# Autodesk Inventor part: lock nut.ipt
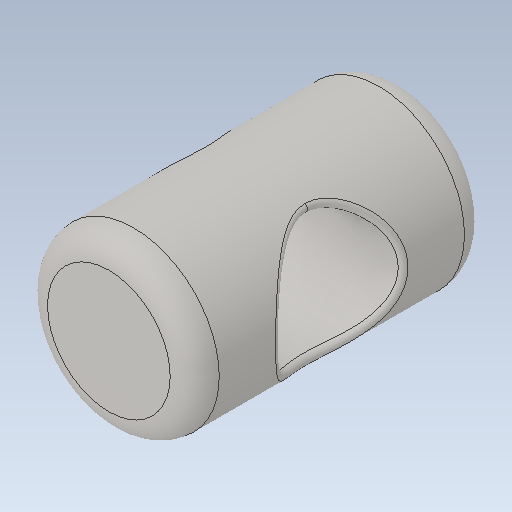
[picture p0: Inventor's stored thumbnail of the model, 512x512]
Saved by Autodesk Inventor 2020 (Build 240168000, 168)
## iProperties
Created: 2017-10
Part Number: lock nut.ipt
Material: Ogólny
Document SubType Name: Modeling
Designer: Tomasz
Density: 1 g/cm^3
Appearance: Domyślna
Sending System: SolidWorks 2017
Last Author: Tomasz
Last Saved: 2017-10-01
Author: Tomasz
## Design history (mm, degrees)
feature "lock nut.ipt"
node "Bryła1"
